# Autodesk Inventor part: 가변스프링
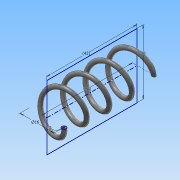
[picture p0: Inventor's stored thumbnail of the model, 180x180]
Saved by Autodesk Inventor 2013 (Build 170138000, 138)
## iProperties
Created: 2015-09
Part Number: 가변스프링
Material: 강철, 탄소
Document SubType Name: Modeling
Designer: Administrator
Density: 7.87 g/cm^3
Mass: 4.91411 g
Surface Area: 12.711 cm^2
Volume: 0.62441 cm^3
Author: Administrator
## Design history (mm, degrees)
sketch "스케치1"
  geometry: L1 (0, 0)-(0, 42); L2 (0, 42)-(8, 42); C1 r 1 at (8, 0)
  constraints: 4 end point, 1 centre point, 1 horizontal alignment, 1 perpendicular, 1 vertical
  dimensions: "d0" = 42 distance of L1.start L1.end (derived); "d1" = 2 diameter of C1; "d2" = 16 diameter of C1.centre L1
feature "코일1" sketch "스케치1" pitch "d3" = 10; turns "d5" = 4; dims "d4" = 42 (= d0), "d6" = 0, angle "d7" = 90 deg, angle "d8" = 90 deg, "d9" = 0, "d10" = 0
sketch "스케치3"
  geometry: L1 (42, 15)-(0, 15); L2 (0, 15)-(0, -15); L3 (0, -15)-(42, -15); L4 (42, -15)-(42, 15); 2 further points
  constraints: 8 end point, 2 coincident, 2 parallel, 1 horizontal, 1 midpoint, 1 perpendicular
  dimensions: "d18" = 30 distance of L3.end L1.start; "d21" = 42 distance of L1.start L1.end (derived)
extrude "돌출2" sketch "스케치3" stored distance "d22" = 10; taper "d23" = 0 deg
node "솔리드1"
